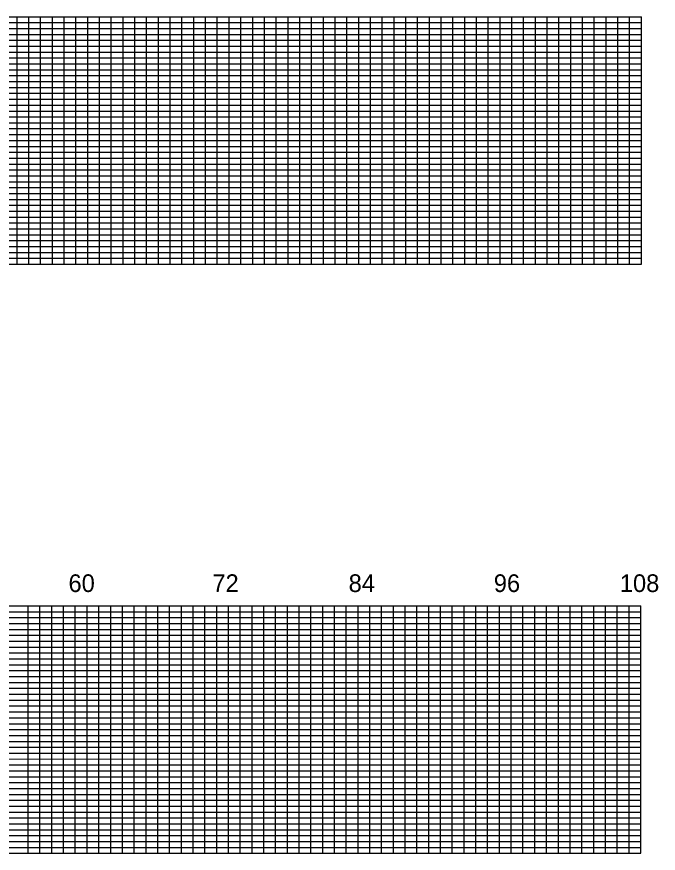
# Model space of a CAD drawing. Extents: x 1950433 to 1956806, y 750939 to 777666.
# Drawn here: x 1954041 to 1956764, y 750964 to 754514 of the extents above; entities that cross this region are included whole.
import ezdxf

# ---------------------------------------------------------------- set-up
doc = ezdxf.new("R2010")
doc.units = 0
doc.layers.add('RD_PD_WallFill', color=7, linetype='Continuous')

msp = doc.modelspace()

# ---------------------------------------------------------------- linework, layer by layer
at = {"layer": 'RD_PD_WallFill'}
for p, q in [((1951342.5, 754514.1), (1956692.5, 754514.2)), ((1951792.5, 754489.1), (1956692.5, 754489.1)), ((1954042.6, 753464.2), (1954042.5, 754514.2)), ((1954092.6, 753464.2), (1954092.5, 754514.2)), ((1954142.6, 753464.2), (1954142.5, 754514.2)), ((1954192.6, 753464.2), (1954192.5, 754514.2)), ((1954242.6, 753464.2), (1954242.5, 754514.2)), ((1954292.6, 753464.2), (1954292.6, 754514.2)), ((1954342.6, 753464.2), (1954342.6, 754514.2)), ((1954392.6, 753464.2), (1954392.6, 754514.2)), ((1954442.6, 753464.1), (1954442.6, 754514.2)), ((1954492.6, 753464.2), (1954492.6, 754514.2)), ((1954542.6, 753464.2), (1954542.6, 754514.2)), ((1954592.6, 753464.2), (1954592.6, 754514.2)), ((1954642.6, 753464.2), (1954642.6, 754514.2)), ((1954692.6, 753464.2), (1954692.6, 754514.2)), ((1954742.5, 753464.1), (1954742.6, 754514.2)), ((1954792.6, 753464.1), (1954792.6, 754514.2)), ((1954842.6, 753464.2), (1954842.6, 754514.2)), ((1954892.5, 753464.2), (1954892.6, 754514.2)), ((1954942.5, 753464.2), (1954942.6, 754514.2)), ((1954992.6, 753464.2), (1954992.6, 754514.2)), ((1955042.6, 753464.2), (1955042.6, 754514.2)), ((1955092.6, 753464.2), (1955092.6, 754514.2)), ((1955142.6, 753464.2), (1955142.6, 754514.2)), ((1955192.6, 753464.2), (1955192.6, 754514.2)), ((1955242.6, 753464.2), (1955242.6, 754514.2)), ((1955292.6, 753464.2), (1955292.6, 754514.2)), ((1955342.6, 753464.2), (1955342.6, 754514.2)), ((1955392.6, 753464.2), (1955392.6, 754514.2)), ((1955442.6, 753464.2), (1955442.6, 754514.2)), ((1955492.6, 753464.2), (1955492.6, 754514.2)), ((1955542.6, 753464.2), (1955542.6, 754514.2)), ((1955592.6, 753464.2), (1955592.6, 754514.2)), ((1955642.6, 753464.2), (1955642.6, 754514.2)), ((1955692.6, 753464.2), (1955692.6, 754514.2)), ((1955742.6, 753464.2), (1955742.6, 754514.2)), ((1955792.6, 753464.2), (1955792.6, 754514.2)), ((1955842.6, 753464.2), (1955842.6, 754514.2)), ((1955892.6, 753464.2), (1955892.6, 754514.2)), ((1955942.6, 753464.2), (1955942.6, 754514.2)), ((1955992.6, 753464.2), (1955992.6, 754514.2)), ((1956042.6, 753464.2), (1956042.6, 754514.2)), ((1956092.6, 753464.2), (1956092.6, 754514.2)), ((1956142.6, 753464.2), (1956142.6, 754514.2)), ((1956192.6, 753464.2), (1956192.6, 754514.2)), ((1956242.6, 753464.2), (1956242.6, 754514.2)), ((1956292.6, 753464.2), (1956292.6, 754514.2)), ((1956342.6, 753464.2), (1956342.6, 754514.2)), ((1956392.6, 753464.2), (1956392.6, 754514.2)), ((1956442.6, 753464.2), (1956442.6, 754514.2)), ((1956492.6, 753464.2), (1956492.6, 754514.2)), ((1956542.6, 753464.2), (1956542.6, 754514.2)), ((1956592.6, 753464.2), (1956592.6, 754514.2)), ((1956642.6, 753464.2), (1956642.6, 754514.2)), ((1956692.6, 753464.2), (1956692.6, 754514.2)), ((1951792.5, 754464.1), (1956692.5, 754464.1)), ((1951792.5, 754439.1), (1956692.5, 754439.1)), ((1951792.5, 754414.2), (1956692.5, 754414.1)), ((1951792.5, 754389.1), (1956692.5, 754389.2)), ((1951342.5, 754364.1), (1956692.5, 754364.1)), ((1951342.5, 754339.1), (1956692.5, 754339.1)), ((1951342.5, 754314.1), (1956692.5, 754314.2)), ((1951342.5, 754289.2), (1956692.5, 754289.1)), ((1951342.5, 754264.2), (1956692.5, 754264.2)), ((1951342.5, 754239.1), (1956692.5, 754239.1)), ((1951342.5, 754214.1), (1956692.5, 754214.1)), ((1951342.5, 754189.2), (1956692.5, 754189.1)), ((1951342.5, 754164.1), (1956692.5, 754164.1)), ((1951342.5, 754139.2), (1956692.5, 754139.1)), ((1951342.5, 754114.1), (1956692.5, 754114.1)), ((1951342.5, 754089.1), (1956692.5, 754089.2)), ((1951342.5, 754064.1), (1956692.5, 754064.1)), ((1951342.5, 754039.1), (1956692.5, 754039.2)), ((1951342.5, 754014.1), (1956692.5, 754014.1)), ((1951342.5, 753989.1), (1956692.5, 753989.1)), ((1951342.5, 753964.2), (1956692.5, 753964.1)), ((1951342.5, 753939.1), (1956692.5, 753939.1)), ((1951342.5, 753914.1), (1956692.5, 753914.1)), ((1951342.5, 753889.1), (1956692.5, 753889.1)), ((1951342.5, 753864.1), (1956692.5, 753864.2)), ((1951342.5, 753839.1), (1956692.5, 753839.1)), ((1951342.5, 753814.1), (1956692.5, 753814.1)), ((1951342.5, 753789.1), (1956692.5, 753789.1)), ((1951342.5, 753764.1), (1956692.5, 753764.1)), ((1951342.5, 753739.1), (1956692.5, 753739.1)), ((1951342.5, 753714.1), (1956692.5, 753714.1)), ((1951342.5, 753689.1), (1956692.5, 753689.1)), ((1951342.5, 753664.1), (1956692.5, 753664.1)), ((1951342.5, 753639.1), (1956692.5, 753639.1)), ((1951342.5, 753614.1), (1956692.5, 753614.1)), ((1951342.5, 753589.1), (1956692.5, 753589.1)), ((1951342.5, 753564.1), (1956692.5, 753564.1)), ((1951342.5, 753539.1), (1956692.5, 753539.1)), ((1951342.5, 753514.1), (1956692.5, 753514.1)), ((1951342.5, 753464.1), (1956692.5, 753464.1)), ((1951392.5, 753489.1), (1956692.5, 753489.1)), ((1951339.9, 752014.1), (1956689.9, 752014.2)), ((1954089.9, 750964.2), (1954089.9, 752014.2)), ((1954139.9, 750964.2), (1954139.9, 752014.2)), ((1954189.9, 750964.2), (1954189.9, 752014.2)), ((1954239.9, 750964.2), (1954239.9, 752014.2)), ((1954289.9, 750964.2), (1954289.9, 752014.2)), ((1954339.9, 750964.2), (1954339.9, 752014.2)), ((1954389.9, 750964.2), (1954389.9, 752014.2)), ((1954439.9, 750964.1), (1954439.9, 752014.2)), ((1954489.9, 750964.2), (1954489.9, 752014.2)), ((1954539.9, 750964.2), (1954539.9, 752014.2)), ((1954589.9, 750964.2), (1954589.9, 752014.2)), ((1954639.9, 750964.2), (1954639.9, 752014.2)), ((1954689.9, 750964.2), (1954689.9, 752014.2)), ((1954739.9, 750964.1), (1954739.9, 752014.2)), ((1954789.9, 750964.1), (1954789.9, 752014.2)), ((1954839.9, 750964.2), (1954839.9, 752014.2)), ((1954889.9, 750964.2), (1954889.9, 752014.2)), ((1954939.9, 750964.2), (1954939.9, 752014.2)), ((1954989.9, 750964.2), (1954989.9, 752014.2)), ((1955039.9, 750964.2), (1955039.9, 752014.2)), ((1955089.9, 750964.2), (1955089.9, 752014.2)), ((1955139.9, 750964.2), (1955139.9, 752014.2)), ((1955189.9, 750964.2), (1955189.9, 752014.2)), ((1955239.9, 750964.2), (1955239.9, 752014.2)), ((1955289.9, 750964.2), (1955289.9, 752014.2)), ((1955339.9, 750964.2), (1955339.9, 752014.2)), ((1955389.9, 750964.2), (1955389.9, 752014.2)), ((1955439.9, 750964.2), (1955439.9, 752014.2)), ((1955489.9, 750964.2), (1955489.9, 752014.2)), ((1955539.9, 750964.2), (1955539.9, 752014.2)), ((1955589.9, 750964.2), (1955589.9, 752014.2)), ((1955639.9, 750964.2), (1955639.9, 752014.2)), ((1955689.9, 750964.2), (1955689.9, 752014.2)), ((1955739.9, 750964.2), (1955739.9, 752014.2)), ((1955789.9, 750964.2), (1955789.9, 752014.2)), ((1955839.9, 750964.2), (1955839.9, 752014.2)), ((1955889.9, 750964.2), (1955889.9, 752014.2)), ((1955939.9, 750964.2), (1955939.9, 752014.2)), ((1955989.9, 750964.2), (1955989.9, 752014.2)), ((1956039.9, 750964.2), (1956039.9, 752014.2)), ((1956089.9, 750964.2), (1956089.9, 752014.2)), ((1956139.9, 750964.2), (1956139.9, 752014.2)), ((1956189.9, 750964.2), (1956189.9, 752014.2)), ((1956239.9, 750964.2), (1956239.9, 752014.2)), ((1956289.9, 750964.2), (1956289.9, 752014.2)), ((1956339.9, 750964.2), (1956339.9, 752014.2)), ((1956389.9, 750964.2), (1956389.9, 752014.2)), ((1956439.9, 750964.2), (1956439.9, 752014.2)), ((1956489.9, 750964.2), (1956489.9, 752014.2)), ((1956539.9, 750964.2), (1956539.9, 752014.2)), ((1956589.9, 750964.2), (1956589.9, 752014.2)), ((1956639.9, 750964.2), (1956639.9, 752014.2)), ((1956689.9, 750964.2), (1956689.9, 752014.2)), ((1951789.9, 751989.1), (1956689.9, 751989.1)), ((1951789.9, 751964.1), (1956689.9, 751964.1)), ((1951789.9, 751939.1), (1956689.9, 751939.1)), ((1951789.9, 751914.2), (1956689.9, 751914.1)), ((1951339.9, 751864.1), (1956689.9, 751864.1)), ((1951789.9, 751889.1), (1956689.9, 751889.2)), ((1951339.9, 751839.1), (1956689.9, 751839.1)), ((1951339.9, 751814.1), (1956689.9, 751814.2)), ((1951339.9, 751789.2), (1956689.9, 751789.1)), ((1951339.9, 751764.2), (1956689.9, 751764.2)), ((1951339.9, 751739.1), (1956689.9, 751739.1)), ((1951339.9, 751714.1), (1956689.9, 751714.1)), ((1951339.9, 751689.2), (1956689.9, 751689.1)), ((1951339.9, 751664.1), (1956689.9, 751664.1)), ((1951339.9, 751639.2), (1956689.9, 751639.1)), ((1951339.9, 751614.1), (1956689.9, 751614.1)), ((1951339.9, 751589.1), (1956689.9, 751589.2)), ((1951339.9, 751564.1), (1956689.9, 751564.1)), ((1951339.9, 751539.1), (1956689.9, 751539.2)), ((1951339.9, 751514.1), (1956689.9, 751514.1)), ((1951339.9, 751489.1), (1956689.9, 751489.1)), ((1951339.9, 751464.2), (1956689.9, 751464.1)), ((1951339.9, 751439.1), (1956689.9, 751439.1)), ((1951339.9, 751414.1), (1956689.9, 751414.1)), ((1951339.9, 751389.1), (1956689.9, 751389.1)), ((1951339.9, 751364.1), (1956689.9, 751364.2)), ((1951339.9, 751339.1), (1956689.9, 751339.1)), ((1951339.9, 751314.1), (1956689.9, 751314.1)), ((1951339.9, 751289.1), (1956689.9, 751289.1)), ((1951339.9, 751264.1), (1956689.9, 751264.1)), ((1951339.9, 751239.1), (1956689.9, 751239.1)), ((1951339.9, 751214.1), (1956689.9, 751214.1)), ((1951339.9, 751189.1), (1956689.9, 751189.1)), ((1951339.9, 751164.1), (1956689.9, 751164.1)), ((1951339.9, 751139.1), (1956689.9, 751139.1)), ((1951339.9, 751114.1), (1956689.9, 751114.1)), ((1951339.9, 751089.1), (1956689.9, 751089.1)), ((1951339.9, 751064.1), (1956689.9, 751064.1)), ((1951339.9, 751039.1), (1956689.9, 751039.1)), ((1951339.9, 751014.1), (1956689.9, 751014.1)), ((1951389.9, 750989.1), (1956689.9, 750989.1)), ((1951339.9, 750964.1), (1956689.9, 750964.1))]:
    msp.add_line(p, q, dxfattribs=at)

# ---------------------------------------------------------------- texts
for s, p in [('60', (1954261, 752072.8)), ('72', (1954871.7, 752072.8)), ('84', (1955449.9, 752072.8)), ('96', (1956066, 752072.8)), ('108', (1956601, 752072.8))]:
    msp.add_text(s, height=75, dxfattribs=at).set_placement(p)

doc.saveas('drawing.dxf')
